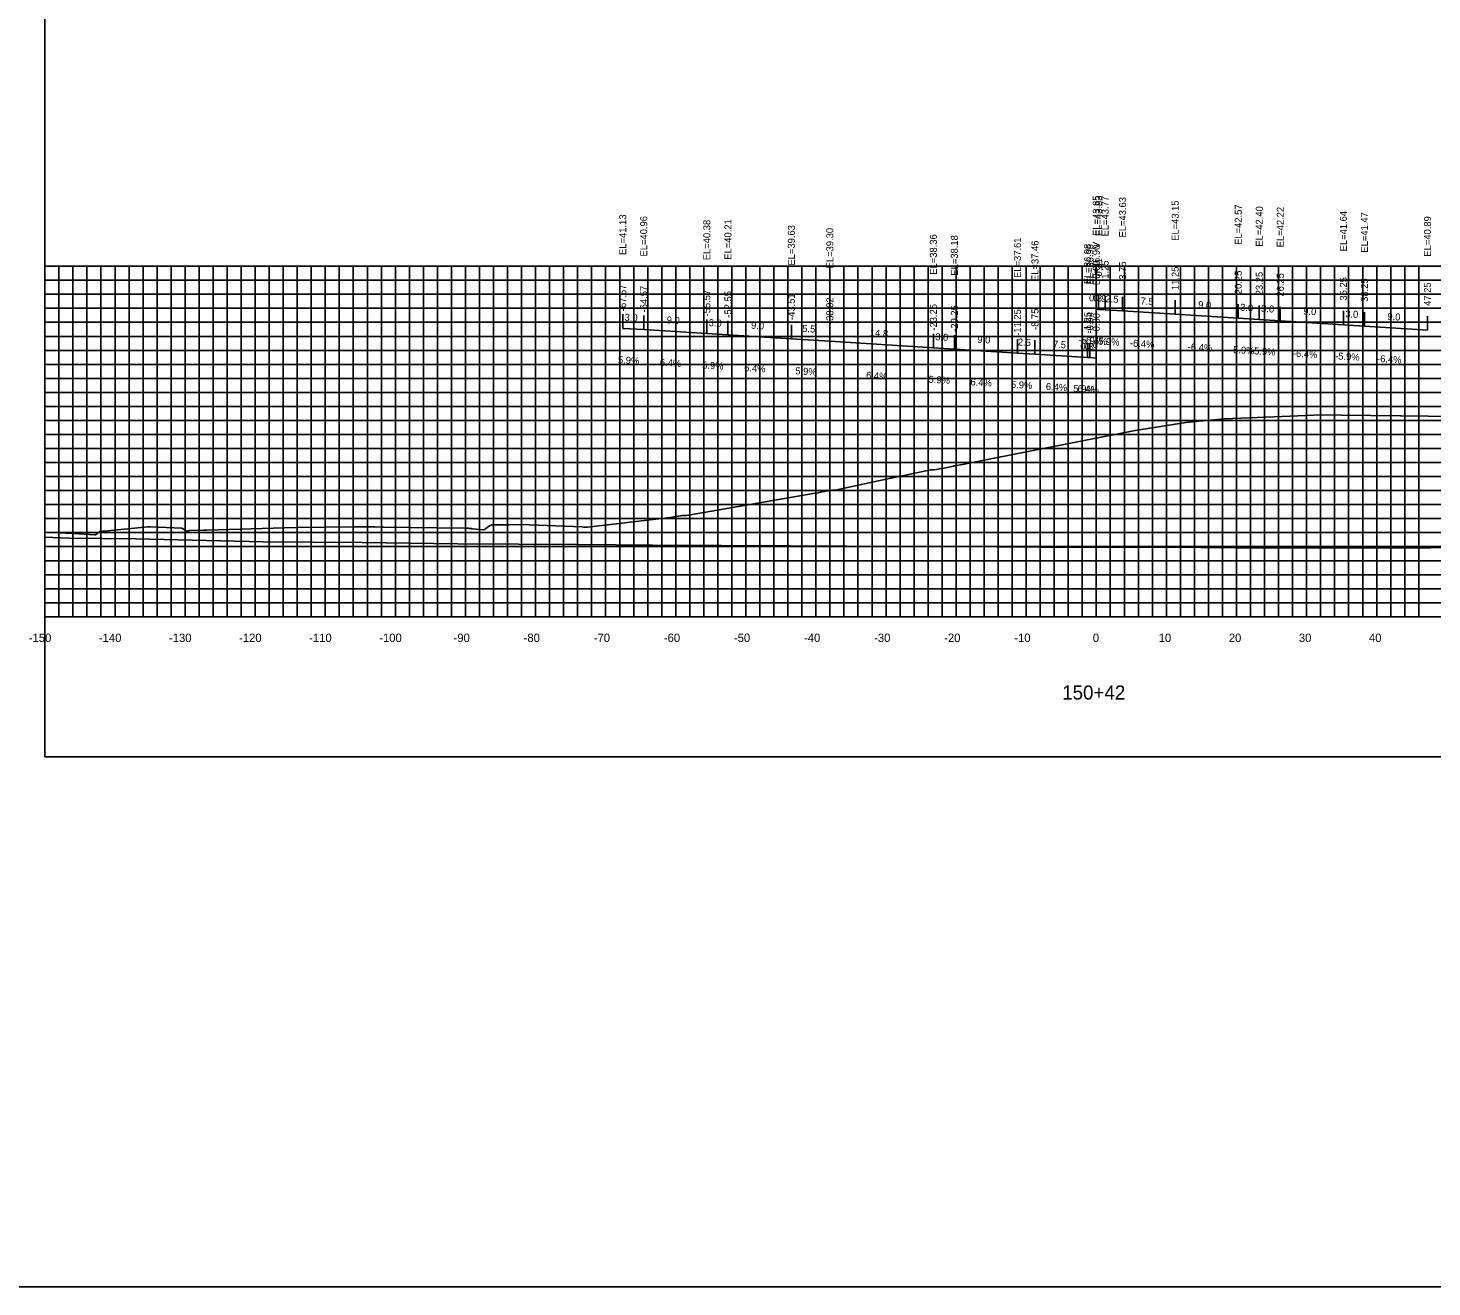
# Model space of a CAD drawing. Extents: x 1800880 to 1818864, y 245271 to 250560.
# Drawn here: x 1810923.3 to 1811123.6, y 246594.2 to 246773.8 of the extents above; entities that cross this region are included whole.
import ezdxf

# ---------------------------------------------------------------- set-up
doc = ezdxf.new("R2010")
doc.units = 0
for name, color, linetype in [('ANNO-TXT', 7, 'Continuous'), ('AXIS', 7, 'Continuous'), ('CL-CNST', 7, 'Continuous'), ('DESIGN - DRAINAGE - Bridges', 7, 'Continuous'), ('Level 32', 7, 'Continuous'), ('Level 37', 7, 'Continuous'), ('Level 46', 7, 'Continuous'), ('Level 62', 7, 'Continuous'), ('SHT-BDR', 7, 'Continuous')]:
    doc.layers.add(name, color=color, linetype=linetype)

msp = doc.modelspace()

# ---------------------------------------------------------------- linework, layer by layer
at = {"layer": 'AXIS'}
msp.add_lwpolyline([(1811075.72, 246733.66), (1811076.03, 246733.64), (1811076.97, 246733.58), (1811079.47, 246733.43), (1811086.97, 246732.95), (1811095.97, 246732.38), (1811098.97, 246732.2), (1811101.97, 246732.02), (1811110.97, 246731.45), (1811113.97, 246731.27), (1811122.97, 246730.69)], dxfattribs=at)
at = {"layer": 'CL-CNST'}
msp.add_lwpolyline([(1810925.72, 246701.89), (1810929.72, 246701.69), (1810930.55, 246701.64), (1810930.67, 246701.64), (1810930.86, 246701.63), (1810931.34, 246701.6), (1810932.86, 246701.49), (1810932.9, 246701.49), (1810932.9, 246701.49), (1810932.9, 246701.49), (1810932.9, 246701.49), (1810932.9, 246701.49), (1810932.92, 246701.51), (1810933.57, 246701.95), (1810933.57, 246701.95), (1810933.92, 246701.99), (1810933.96, 246702), (1810934.19, 246702.02), (1810940.4, 246702.65), (1810940.72, 246702.65), (1810941.94, 246702.57), (1810945.24, 246702.44), (1810945.48, 246702.29), (1810945.88, 246702.01), (1810946.13, 246702.06), (1810946.21, 246702.07), (1810946.34, 246702.09), (1810946.36, 246702.09), (1810948.35, 246702.15), (1810948.84, 246702.16), (1810959.88, 246702.48), (1810961.82, 246702.51), (1810969.83, 246702.62), (1810970.19, 246702.62), (1810970.27, 246702.62), (1810970.29, 246702.62), (1810971.38, 246702.62), (1810971.92, 246702.61), (1810972.24, 246702.61), (1810972.46, 246702.61), (1810972.61, 246702.61), (1810972.72, 246702.61), (1810972.81, 246702.61), (1810973.82, 246702.6), (1810973.9, 246702.61), (1810973.91, 246702.61), (1810973.92, 246702.61), (1810973.92, 246702.6), (1810973.97, 246702.6), (1810973.97, 246702.6), (1810974.01, 246702.6), (1810985.64, 246702.43), (1810986.15, 246702.42), (1810986.15, 246702.42), (1810986.28, 246702.4), (1810986.39, 246702.39), (1810986.49, 246702.38), (1810986.58, 246702.37), (1810986.67, 246702.36), (1810986.74, 246702.35), (1810988.35, 246702.19), (1810988.63, 246702.37), (1810989.02, 246702.66), (1810989.25, 246702.83), (1810989.48, 246702.9), (1810991.83, 246702.9), (1810991.9, 246702.9), (1810993.64, 246702.96), (1811002.38, 246702.61), (1811002.61, 246702.6), (1811002.64, 246702.6), (1811003.11, 246702.6), (1811014.93, 246703.98), (1811014.96, 246703.98), (1811016.68, 246704.23), (1811017.21, 246704.24), (1811017.26, 246704.25), (1811035.62, 246707.43), (1811036.04, 246707.5), (1811036.12, 246707.52), (1811037.97, 246707.88), (1811038.43, 246707.88), (1811038.47, 246707.88), (1811046.42, 246709.55), (1811047.79, 246709.85), (1811048.49, 246710), (1811052.08, 246710.75), (1811052.58, 246710.76), (1811053.97, 246711.02), (1811055.35, 246711.3), (1811055.45, 246711.32), (1811056.65, 246711.53), (1811061.17, 246712.43), (1811081.25, 246716.39), (1811088.5, 246717.53), (1811090.8, 246717.74), (1811091.01, 246717.74), (1811092.97, 246717.92), (1811093.96, 246718.01), (1811101.04, 246718.31), (1811107.9, 246718.59), (1811110.7, 246718.55), (1811119.07, 246718.44), (1811119.28, 246718.44), (1811130.62, 246718.33)], dxfattribs=at)
at = {"layer": 'DESIGN - DRAINAGE - Bridges'}
for p, q in [((1810925.66, 246739.8), (1810925.72, 246739.8)), ((1810925.72, 246689.8), (1810925.72, 246739.8)), ((1810925.66, 246729.8), (1810925.72, 246729.8)), ((1810925.66, 246719.8), (1810925.72, 246719.8)), ((1810925.66, 246709.8), (1810925.72, 246709.8)), ((1810925.66, 246699.8), (1810925.72, 246699.8)), ((1810925.66, 246689.8), (1810925.72, 246689.8)), ((1810925.72, 246689.8), (1811225.72, 246689.8)), ((1810925.72, 246689.74), (1810925.72, 246689.8)), ((1810935.72, 246689.74), (1810935.72, 246689.8)), ((1810945.72, 246689.74), (1810945.72, 246689.8)), ((1810955.72, 246689.74), (1810955.72, 246689.8)), ((1810965.72, 246689.74), (1810965.72, 246689.8)), ((1810975.72, 246689.74), (1810975.72, 246689.8)), ((1810985.72, 246689.74), (1810985.72, 246689.8)), ((1810995.72, 246689.74), (1810995.72, 246689.8)), ((1811005.72, 246689.74), (1811005.72, 246689.8)), ((1811015.72, 246689.74), (1811015.72, 246689.8)), ((1811025.72, 246689.74), (1811025.72, 246689.8)), ((1811035.72, 246689.74), (1811035.72, 246689.8)), ((1811045.72, 246689.74), (1811045.72, 246689.8)), ((1811055.72, 246689.74), (1811055.72, 246689.8)), ((1811065.72, 246689.74), (1811065.72, 246689.8)), ((1811075.72, 246689.74), (1811075.72, 246689.8)), ((1811085.72, 246689.74), (1811085.72, 246689.8)), ((1811095.72, 246689.74), (1811095.72, 246689.8)), ((1811105.72, 246689.74), (1811105.72, 246689.8)), ((1811115.72, 246689.74), (1811115.72, 246689.8))]:
    msp.add_line(p, q, dxfattribs=at)
at = {"layer": 'Level 32'}
msp.add_lwpolyline([(1807748.28, 249582.47), (1811531.79, 249582.47), (1811531.79, 246594.22), (1807748.28, 246594.22)], close=True, dxfattribs=at)
at = {"layer": 'Level 37'}
for p, q in [((1811075.72, 246733.66), (1811075.72, 246735.66)), ((1811076.03, 246733.64), (1811076.03, 246735.64)), ((1811076.97, 246733.58), (1811076.97, 246735.58)), ((1811079.47, 246733.43), (1811079.47, 246735.43)), ((1811086.97, 246732.95), (1811086.97, 246734.95)), ((1811095.97, 246732.38), (1811095.97, 246734.38)), ((1811098.97, 246732.2), (1811098.97, 246734.2)), ((1811101.97, 246732.02), (1811101.97, 246734.02)), ((1811008.15, 246730.94), (1811008.15, 246732.94)), ((1811011.15, 246730.76), (1811011.15, 246732.76)), ((1811020.15, 246730.19), (1811020.15, 246732.19)), ((1811023.17, 246730.01), (1811023.17, 246732.01)), ((1811110.97, 246731.45), (1811110.97, 246733.45)), ((1811113.97, 246731.27), (1811113.97, 246733.27)), ((1811122.97, 246730.69), (1811122.97, 246732.69)), ((1811032.21, 246729.43), (1811032.21, 246731.43)), ((1811037.7, 246729.11), (1811037.7, 246731.11)), ((1811052.47, 246728.16), (1811052.47, 246730.16)), ((1811055.47, 246727.99), (1811055.47, 246729.99)), ((1811064.47, 246727.41), (1811064.47, 246729.41)), ((1811066.97, 246727.26), (1811066.97, 246729.26)), ((1811074.47, 246726.78), (1811074.47, 246728.78)), ((1811074.78, 246726.76), (1811074.78, 246728.76)), ((1811075.71, 246726.7), (1811075.71, 246728.7))]:
    msp.add_line(p, q, dxfattribs=at)
msp.add_lwpolyline([(1810925.72, 246669.8), (1811225.72, 246669.8), (1811225.72, 246859.8), (1810925.72, 246859.8)], close=True, dxfattribs=at)
at = {"layer": 'Level 46'}
for p, q in [((1810925.72, 246739.8), (1811225.72, 246739.8)), ((1810925.72, 246689.8), (1810925.72, 246739.8)), ((1810927.72, 246689.8), (1810927.72, 246739.8)), ((1810929.72, 246689.8), (1810929.72, 246739.8)), ((1810931.72, 246689.8), (1810931.72, 246739.8)), ((1810933.72, 246689.8), (1810933.72, 246739.8)), ((1810935.72, 246689.8), (1810935.72, 246739.8)), ((1810937.72, 246689.8), (1810937.72, 246739.8)), ((1810939.72, 246689.8), (1810939.72, 246739.8)), ((1810941.72, 246689.8), (1810941.72, 246739.8)), ((1810943.72, 246689.8), (1810943.72, 246739.8)), ((1810945.72, 246689.8), (1810945.72, 246739.8)), ((1810947.72, 246689.8), (1810947.72, 246739.8)), ((1810949.72, 246689.8), (1810949.72, 246739.8)), ((1810951.72, 246689.8), (1810951.72, 246739.8)), ((1810953.72, 246689.8), (1810953.72, 246739.8)), ((1810955.72, 246689.8), (1810955.72, 246739.8)), ((1810957.72, 246689.8), (1810957.72, 246739.8)), ((1810959.72, 246689.8), (1810959.72, 246739.8)), ((1810961.72, 246689.8), (1810961.72, 246739.8)), ((1810963.72, 246689.8), (1810963.72, 246739.8)), ((1810965.72, 246689.8), (1810965.72, 246739.8)), ((1810967.72, 246689.8), (1810967.72, 246739.8)), ((1810969.72, 246689.8), (1810969.72, 246739.8)), ((1810971.72, 246689.8), (1810971.72, 246739.8)), ((1810973.72, 246689.8), (1810973.72, 246739.8)), ((1810975.72, 246689.8), (1810975.72, 246739.8)), ((1810977.72, 246689.8), (1810977.72, 246739.8)), ((1810979.72, 246689.8), (1810979.72, 246739.8)), ((1810981.72, 246689.8), (1810981.72, 246739.8)), ((1810983.72, 246689.8), (1810983.72, 246739.8)), ((1810985.72, 246689.8), (1810985.72, 246739.8)), ((1810987.72, 246689.8), (1810987.72, 246739.8)), ((1810989.72, 246689.8), (1810989.72, 246739.8)), ((1810991.72, 246689.8), (1810991.72, 246739.8)), ((1810993.72, 246689.8), (1810993.72, 246739.8)), ((1810995.72, 246689.8), (1810995.72, 246739.8)), ((1810997.72, 246689.8), (1810997.72, 246739.8)), ((1810999.72, 246689.8), (1810999.72, 246739.8)), ((1811001.72, 246689.8), (1811001.72, 246739.8)), ((1811003.72, 246689.8), (1811003.72, 246739.8)), ((1811005.72, 246689.8), (1811005.72, 246739.8)), ((1811007.72, 246689.8), (1811007.72, 246739.8)), ((1811009.72, 246689.8), (1811009.72, 246739.8)), ((1811011.72, 246689.8), (1811011.72, 246739.8)), ((1811013.72, 246689.8), (1811013.72, 246739.8)), ((1811015.72, 246689.8), (1811015.72, 246739.8)), ((1811017.72, 246689.8), (1811017.72, 246739.8)), ((1811019.72, 246689.8), (1811019.72, 246739.8)), ((1811021.72, 246689.8), (1811021.72, 246739.8)), ((1811023.72, 246689.8), (1811023.72, 246739.8)), ((1811025.72, 246689.8), (1811025.72, 246739.8)), ((1811027.72, 246689.8), (1811027.72, 246739.8)), ((1811029.72, 246689.8), (1811029.72, 246739.8)), ((1811031.72, 246689.8), (1811031.72, 246739.8)), ((1811033.72, 246689.8), (1811033.72, 246739.8)), ((1811035.72, 246689.8), (1811035.72, 246739.8)), ((1811037.72, 246689.8), (1811037.72, 246739.8)), ((1811039.72, 246689.8), (1811039.72, 246739.8)), ((1811041.72, 246689.8), (1811041.72, 246739.8)), ((1811043.72, 246689.8), (1811043.72, 246739.8)), ((1811045.72, 246689.8), (1811045.72, 246739.8)), ((1811047.72, 246689.8), (1811047.72, 246739.8)), ((1811049.72, 246689.8), (1811049.72, 246739.8)), ((1811051.72, 246689.8), (1811051.72, 246739.8)), ((1811053.72, 246689.8), (1811053.72, 246739.8)), ((1811055.72, 246689.8), (1811055.72, 246739.8)), ((1811057.72, 246689.8), (1811057.72, 246739.8)), ((1811059.72, 246689.8), (1811059.72, 246739.8)), ((1811061.72, 246689.8), (1811061.72, 246739.8)), ((1811063.72, 246689.8), (1811063.72, 246739.8)), ((1811065.72, 246689.8), (1811065.72, 246739.8)), ((1811067.72, 246689.8), (1811067.72, 246739.8)), ((1811069.72, 246689.8), (1811069.72, 246739.8)), ((1811071.72, 246689.8), (1811071.72, 246739.8)), ((1811073.72, 246689.8), (1811073.72, 246739.8)), ((1811075.72, 246689.8), (1811075.72, 246739.8)), ((1811077.72, 246689.8), (1811077.72, 246739.8)), ((1811079.72, 246689.8), (1811079.72, 246739.8)), ((1811081.72, 246689.8), (1811081.72, 246739.8)), ((1811083.72, 246689.8), (1811083.72, 246739.8)), ((1811085.72, 246689.8), (1811085.72, 246739.8)), ((1811087.72, 246689.8), (1811087.72, 246739.8)), ((1811089.72, 246689.8), (1811089.72, 246739.8)), ((1811091.72, 246689.8), (1811091.72, 246739.8)), ((1811093.72, 246689.8), (1811093.72, 246739.8)), ((1811095.72, 246689.8), (1811095.72, 246739.8)), ((1811097.72, 246689.8), (1811097.72, 246739.8)), ((1811099.72, 246689.8), (1811099.72, 246739.8)), ((1811101.72, 246689.8), (1811101.72, 246739.8)), ((1811103.72, 246689.8), (1811103.72, 246739.8)), ((1811105.72, 246689.8), (1811105.72, 246739.8)), ((1811107.72, 246689.8), (1811107.72, 246739.8)), ((1811109.72, 246689.8), (1811109.72, 246739.8)), ((1811111.72, 246689.8), (1811111.72, 246739.8)), ((1811113.72, 246689.8), (1811113.72, 246739.8)), ((1811115.72, 246689.8), (1811115.72, 246739.8)), ((1811117.72, 246689.8), (1811117.72, 246739.8)), ((1811119.72, 246689.8), (1811119.72, 246739.8)), ((1811121.72, 246689.8), (1811121.72, 246739.8)), ((1810925.72, 246737.8), (1811225.72, 246737.8)), ((1810925.72, 246735.8), (1811225.72, 246735.8)), ((1810925.72, 246733.8), (1811225.72, 246733.8)), ((1810925.72, 246731.8), (1811225.72, 246731.8)), ((1810925.72, 246729.8), (1811225.72, 246729.8)), ((1810925.72, 246727.8), (1811225.72, 246727.8)), ((1810925.72, 246725.8), (1811225.72, 246725.8)), ((1810925.72, 246723.8), (1811225.72, 246723.8)), ((1810925.72, 246721.8), (1811225.72, 246721.8)), ((1810925.72, 246719.8), (1811225.72, 246719.8)), ((1810925.72, 246717.8), (1811225.72, 246717.8)), ((1810925.72, 246715.8), (1811225.72, 246715.8)), ((1810925.72, 246713.8), (1811225.72, 246713.8)), ((1810925.72, 246711.8), (1811225.72, 246711.8)), ((1810925.72, 246709.8), (1811225.72, 246709.8)), ((1810925.72, 246707.8), (1811225.72, 246707.8)), ((1810925.72, 246705.8), (1811225.72, 246705.8)), ((1810925.72, 246703.8), (1811225.72, 246703.8)), ((1810925.72, 246701.8), (1811225.72, 246701.8)), ((1810925.72, 246699.8), (1811225.72, 246699.8)), ((1810925.72, 246697.8), (1811225.72, 246697.8)), ((1810925.72, 246695.8), (1811225.72, 246695.8)), ((1810925.72, 246693.8), (1811225.72, 246693.8)), ((1810925.72, 246691.8), (1811225.72, 246691.8)), ((1810925.72, 246689.8), (1811225.72, 246689.8))]:
    msp.add_line(p, q, dxfattribs=at)
at = {"layer": 'Level 62'}
for points in [[(1811008.15, 246730.94), (1811011.15, 246730.76), (1811020.15, 246730.19), (1811023.17, 246730.01), (1811032.21, 246729.43), (1811037.7, 246729.11), (1811052.47, 246728.16), (1811055.47, 246727.99), (1811064.47, 246727.41), (1811066.97, 246727.26), (1811074.47, 246726.78), (1811074.78, 246726.76), (1811075.71, 246726.7)], [(1810925.72, 246701.14), (1810929.11, 246701.01), (1810938.68, 246700.91), (1810956.87, 246700.51), (1810970.98, 246700.39), (1810984.62, 246700.22), (1811001.9, 246700.11), (1811012.38, 246700.01), (1811031.98, 246699.92), (1811040.13, 246699.85), (1811061.53, 246699.78), (1811067.89, 246699.72), (1811090.7, 246699.69), (1811095.65, 246699.65), (1811119.6, 246699.65), (1811123.4, 246699.62), (1811148.31, 246699.66), (1811151.16, 246699.64), (1811176.86, 246699.72), (1811178.91, 246699.72), (1811205.3, 246699.84), (1811206.67, 246699.85), (1811225.72, 246699.95)]]:
    msp.add_lwpolyline(points, dxfattribs=at)

# ---------------------------------------------------------------- texts
for s, p in [('-150', (1810923.42, 246686.2)), ('-140', (1810933.42, 246686.2)), ('-130', (1810943.42, 246686.2)), ('-120', (1810953.42, 246686.2)), ('-110', (1810963.42, 246686.2)), ('-100', (1810973.42, 246686.2)), ('-90', (1810984.02, 246686.2)), ('-80', (1810994.02, 246686.2)), ('-70', (1811004.02, 246686.2)), ('-60', (1811014.02, 246686.2)), ('-50', (1811024.02, 246686.2)), ('-40', (1811034.02, 246686.2)), ('-30', (1811044.02, 246686.2)), ('-20', (1811054.02, 246686.2)), ('-10', (1811064.02, 246686.2)), ('0', (1811075.22, 246686.2)), ('10', (1811084.62, 246686.2)), ('20', (1811094.62, 246686.2)), ('30', (1811104.62, 246686.2)), ('40', (1811114.62, 246686.2))]:
    msp.add_text(s, height=1.2).set_placement(p)
at = {"layer": 'ANNO-TXT'}
for s, rotation, p in [('0.3', 356.6368, (1811074.66, 246734.82)), ('0.9', 356.3368, (1811075.29, 246734.79)), ('2.5', 356.6368, (1811077, 246734.68)), ('7.5', 356.3368, (1811082.01, 246734.37)), ('9.0', 356.3368, (1811090.22, 246733.85)), ('3.0', 356.6368, (1811096.21, 246733.46)), ('3.0', 356.6368, (1811099.21, 246733.29)), ('9.0', 356.3368, (1811105.22, 246732.92)), ('3.0', 356.6368, (1811008.4, 246732.03)), ('9.0', 356.3368, (1811014.4, 246731.66)), ('3.0', 356.6368, (1811020.4, 246731.27)), ('9.0', 356.3368, (1811026.44, 246730.9)), ('3.0', 356.6368, (1811111.21, 246732.53)), ('9.0', 356.3368, (1811117.22, 246732.16)), ('5.5', 356.6368, (1811033.74, 246730.44)), ('14.8', 356.3368, (1811043.38, 246729.85)), ('3.0', 356.6368, (1811052.71, 246729.25)), ('9.0', 356.3368, (1811058.72, 246728.88)), ('-5.9%', 356.6368, (1811073.18, 246728.8)), ('2.5', 356.6368, (1811064.5, 246728.51)), ('7.5', 356.3368, (1811069.51, 246728.2)), ('0.3', 356.6368, (1811073.41, 246727.95)), ('-6.4%', 356.3368, (1811073.78, 246728.77)), ('0.9', 356.3368, (1811074.04, 246727.91)), ('-5.9%', 356.6368, (1811075.52, 246728.66)), ('-6.4%', 356.3368, (1811080.49, 246728.36)), ('-6.4%', 356.3368, (1811088.74, 246727.83)), ('-5.9%', 356.6368, (1811094.77, 246727.44)), ('-5.9%', 356.6368, (1811097.77, 246727.26)), ('-6.4%', 356.3368, (1811103.75, 246726.9)), ('5.9%', 356.6368, (1811007.45, 246725.97)), ('6.4%', 356.3368, (1811013.42, 246725.61)), ('5.9%', 356.6368, (1811019.46, 246725.22)), ('6.4%', 356.3368, (1811025.46, 246724.85)), ('-5.9%', 356.6368, (1811109.77, 246726.51)), ('-6.4%', 356.3368, (1811115.75, 246726.15)), ('5.9%', 356.6368, (1811032.75, 246724.39)), ('6.4%', 356.3368, (1811042.85, 246723.77)), ('5.9%', 356.6368, (1811051.77, 246723.19)), ('6.4%', 356.3368, (1811057.74, 246722.83)), ('5.9%', 356.6368, (1811063.52, 246722.46)), ('6.4%', 356.3368, (1811068.49, 246722.16)), ('5.9%', 356.6368, (1811072.42, 246721.89)), ('6.4%', 356.3368, (1811073.02, 246721.87))]:
    msp.add_text(s, height=1, rotation=rotation, dxfattribs=at).set_placement(p)
at = {"layer": 'DESIGN - DRAINAGE - Bridges'}
for s, height, p in [('>', 1.5, (1811075.11, 246742.05)), ('-', 0.0001, (1810925.72, 246689.8))]:
    msp.add_text(s, height=height, dxfattribs=at).set_placement(p)
at = {"layer": 'Level 32'}
msp.add_text('150+42', height=2, dxfattribs=at).set_placement((1811070.85, 246678))
at = {"layer": 'SHT-BDR'}
for s, p in [('EL=43.85', (1811076.22, 246744.13)), ('EL=43.83', (1811076.53, 246744.11)), ('EL=43.77', (1811077.47, 246744.05)), ('EL=43.63', (1811079.97, 246743.9)), ('EL=43.15', (1811087.47, 246743.42)), ('EL=42.57', (1811096.47, 246742.85)), ('EL=42.40', (1811099.47, 246742.59)), ('EL=42.22', (1811102.47, 246742.5)), ('EL=41.13', (1811008.65, 246741.41)), ('EL=40.96', (1811011.65, 246741.19)), ('EL=40.38', (1811020.65, 246740.66)), ('EL=40.21', (1811023.67, 246740.73)), ('EL=41.64', (1811111.47, 246741.92)), ('EL=41.47', (1811114.47, 246741.74)), ('EL=40.89', (1811123.47, 246741.17)), ('EL=39.63', (1811032.71, 246739.9)), ('EL=39.30', (1811038.2, 246739.5)), ('EL=38.36', (1811052.97, 246738.59)), ('EL=38.18', (1811055.97, 246738.46)), ('EL=37.61', (1811064.97, 246738.13)), ('EL=37.46', (1811067.47, 246737.69)), ('EL=36.98', (1811074.97, 246737.25)), ('EL=36.96', (1811075.28, 246737.19)), ('EL=36.90', (1811076.21, 246737.1)), ('0.00', (1811076.22, 246738.02)), ('0.31', (1811076.53, 246738.33)), ('1.25', (1811077.47, 246738.02)), ('3.75', (1811079.97, 246737.87)), ('11.25', (1811087.47, 246736.4)), ('20.25', (1811096.47, 246735.82)), ('23.25', (1811099.47, 246735.65)), ('26.25', (1811102.47, 246735.47)), ('35.25', (1811111.47, 246734.9)), ('38.25', (1811114.47, 246734.72)), ('-67.57', (1811008.65, 246733.4)), ('-64.57', (1811011.65, 246733.22)), ('-55.57', (1811020.65, 246732.64)), ('-52.55', (1811023.67, 246732.47)), ('-43.51', (1811032.71, 246732.14)), ('47.25', (1811123.47, 246734.14)), ('-38.02', (1811038.2, 246731.56)), ('-23.25', (1811052.97, 246730.62)), ('-20.25', (1811055.97, 246730.44)), ('-11.25', (1811064.97, 246729.87)), ('-8.75', (1811067.47, 246730.71)), ('-1.25', (1811074.97, 246730.23)), ('-0.94', (1811075.28, 246730.21)), ('-0.00', (1811076.21, 246730.07))]:
    msp.add_text(s, height=1, rotation=90, dxfattribs=at).set_placement(p)

doc.saveas('drawing.dxf')
